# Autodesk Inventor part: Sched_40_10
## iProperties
Shininess: 64.0
Length Units: 11272
Angle Units: 11279
Time Units: 11290
Mass Units: 11286
Length Display Precision: 3
Angle Display Precision: 2
Compacted: True
Part Number: Sched_40_10
Document SubType Name: Modeling
Created: 2005-05
Designer: John Blackburn
Manufacturer: Standard
Standards Organization: Custom
Material: Aluminum-6061
Density: 0.0
Volumn: 0.0
Area: 0.0
PropertySet Name: Model Information
Control State: 0
Master: False
Checked Out: False
Author: John Blackburn
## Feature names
1. Extrusion1
